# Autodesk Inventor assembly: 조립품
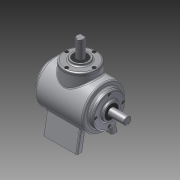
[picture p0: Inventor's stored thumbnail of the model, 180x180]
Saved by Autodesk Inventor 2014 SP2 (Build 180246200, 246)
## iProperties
Created: 2015-01
Part Number: 조립품
Document SubType Name: Assembly
Designer: 201-06
Author: 201-06
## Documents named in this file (15)
- C:\Users\201-06\Desktop\450105V1004\답안조립품.iam
- C:\Users\201-06\Desktop\450105V1004\본체.ipt
- C:\Users\201-06\Desktop\450105V1004\커버.ipt
- C:\Users\201-06\Desktop\450105V1004\커버2.ipt
- C:\Users\201-06\Desktop\450105V1004\메인 축.ipt
- 메인 축.ipt
- C:\Users\201-06\Desktop\450105V1004\서브 축.ipt
- 서브 축.ipt
- C:\Users\201-06\Desktop\450105V1004\메인 베벨기어.ipt
- C:\Users\201-06\Desktop\450105V1004\서브 베벨기어.ipt
- C:\Users\201-06\Desktop\450105V1004\베어링 6203.ipt
- C:\Users\201-06\Desktop\450105V1004\오일실.ipt
- C:\Users\201-06\Desktop\450105V1004\키 5x5.ipt
- C:\Users\201-06\Desktop\450105V1004\키 4x4.ipt
- C:\Users\201-06\Desktop\450105V1004\M4.ipt
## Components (12 placed, 1 different names)
1. M4:2
2. M4:4
3. M4:5
4. M4:6
5. M4:3
6. M4:7
7. M4:8
8. M4:9
9. M4:1
10. M4:10
11. M4:11
12. M4:12
